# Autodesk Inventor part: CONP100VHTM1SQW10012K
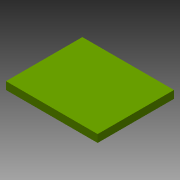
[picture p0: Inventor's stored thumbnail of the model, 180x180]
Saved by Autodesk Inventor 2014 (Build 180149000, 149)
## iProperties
Shininess: 64.0
Length Units: 11272
Angle Units: 11279
Time Units: 11290
Mass Units: 11286
Length Display Precision: 3
Angle Display Precision: 2
Compacted: True
Part Number: CONP100VHTM1SQW10012K
Document SubType Name: Modeling
Created: 2003-04
Designer: t_enrig
Manufacturer: Standard
Standards Organization: Custom
Density: 1 g/cm^3
Mass: 1.96645 g
Surface Area: 18.3225 cm^2
Volume: 1.96645 cm^3
Material: Generic
Appearance: TranslatedColorStyle
Density: 0.0
Volumn: 0.0
Area: 0.0
PropertySet Name: Model Information
Control State: 0
Master: False
Checked Out: False
Author: t_enrig
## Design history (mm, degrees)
feature "Base1"
body "Solid1"
